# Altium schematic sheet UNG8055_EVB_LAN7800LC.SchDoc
size 416 x 264 mm; DocumentNumber: 2; SheetNumber: 2; SheetTotal: 2; PageTitle: LAN7800, RJ45 MagJack, USB Type-C Plug; PageSetup: Record=PageOptions¦CenterHorizontal=True¦CenterVertical=True¦PrintScale=1.02¦XCorrection=1.00¦YCorrection=1.00¦PrintKind=0¦BorderSize=5000000¦LeftOffset=0¦BottomOffset=0¦Orientation=2¦PaperLength=1000¦PaperWidth=1000¦Scale=100¦PaperSource=7¦PrintQuality=-3¦MediaType=1¦DitherType=10¦PrintScaleMode=1¦PaperKind=11 x 17¦PaperIndex=119
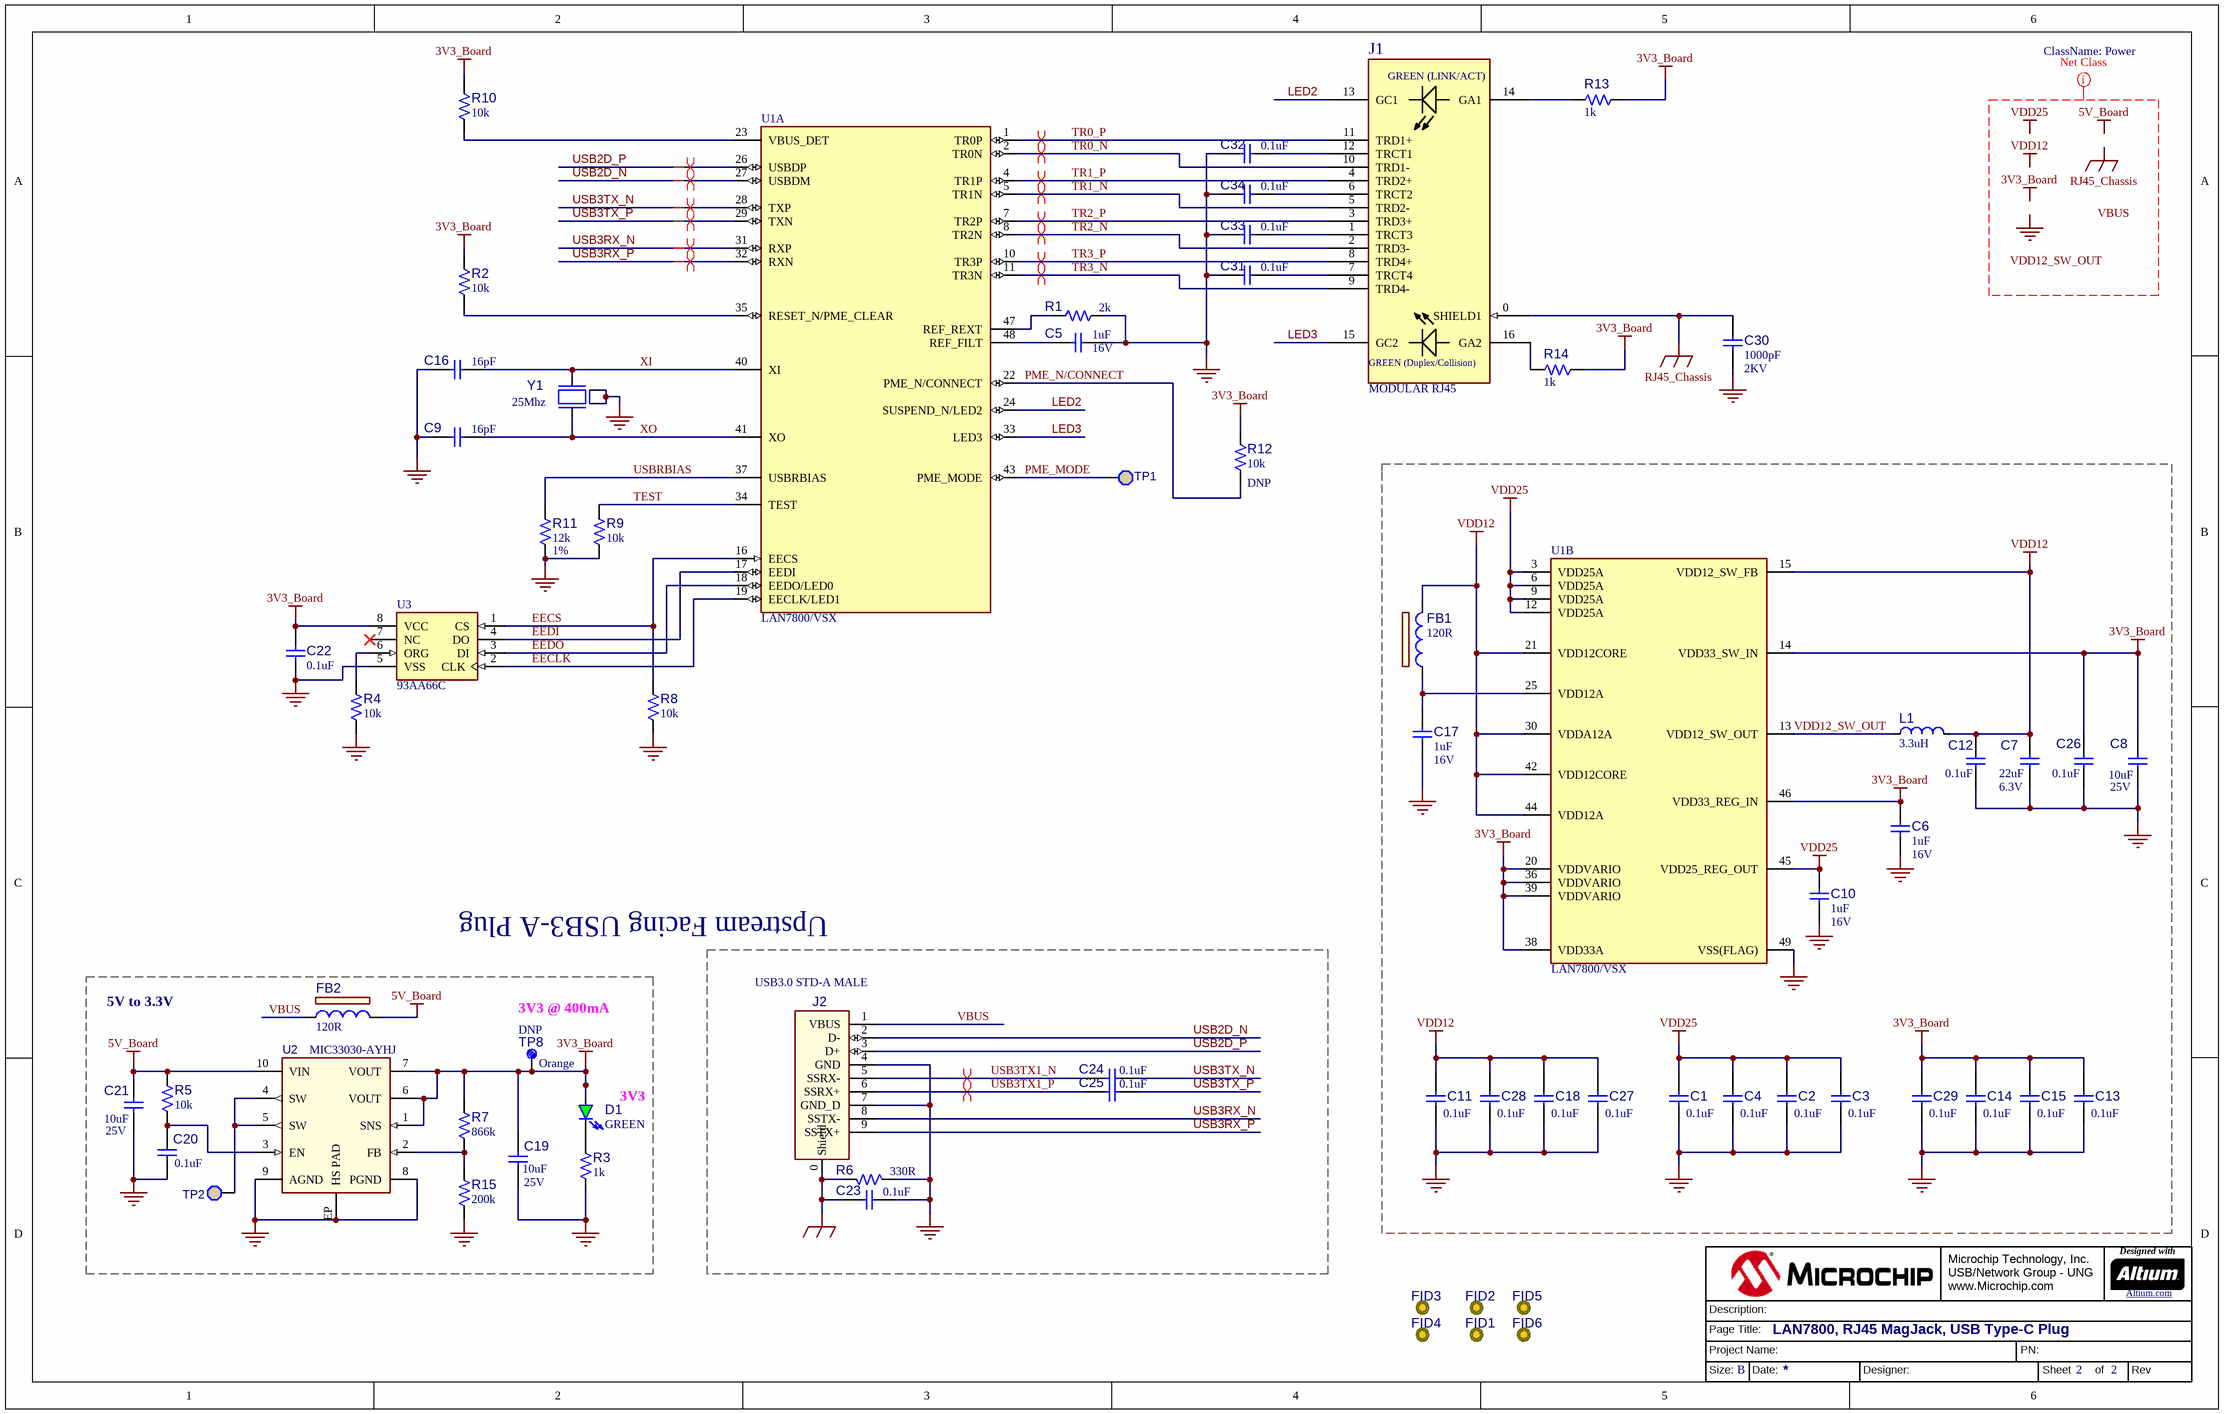
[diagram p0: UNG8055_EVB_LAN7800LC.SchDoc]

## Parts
?  (no value)  (graphical)
C1  value 0.1uF  [CAP_C_0402]  (hidden comment: Capacitor NP)
C2  value 0.1uF  [CAP_C_0402]  (hidden comment: Capacitor NP)
C3  value 0.1uF  [CAP_C_0402]  (hidden comment: Capacitor NP)
C4  value 0.1uF  [CAP_C_0402]  (hidden comment: Capacitor NP)
C5  value 1uF  Voltage: 16V  [CAP_C_0402]  (hidden comment: Capacitor NP)
C6  value 1uF  Voltage: 16V  [CAP_C_0402]  (hidden comment: Capacitor NP)
C7  value 22uF  Voltage: 6.3V  [CAP_C_0603]  (hidden comment: Capacitor NP)
C8  value 10uF  Voltage: 25V  [CAP_C_0603]  (hidden comment: Capacitor NP)
C9  value 16pF  [CAP_C_0402]  (hidden comment: Capacitor NP)
C10  value 1uF  Voltage: 16V  [CAP_C_0402]  (hidden comment: Capacitor NP)
C11  value 0.1uF  [CAP_C_0402]  (hidden comment: Capacitor NP)
C12  value 0.1uF  [CAP_C_0402]  (hidden comment: Capacitor NP)
C13  value 0.1uF  [CAP_C_0402]  (hidden comment: Capacitor NP)
C14  value 0.1uF  [CAP_C_0402]  (hidden comment: Capacitor NP)
C15  value 0.1uF  [CAP_C_0402]  (hidden comment: Capacitor NP)
C16  value 16pF  [CAP_C_0402]  (hidden comment: Capacitor NP)
C17  value 1uF  Voltage: 16V  [CAP_C_0402]  (hidden comment: Capacitor NP)
C18  value 0.1uF  [CAP_C_0402]  (hidden comment: Capacitor NP)
C19  value 10uF  Voltage: 25V  [CAP_C_0603]  (hidden comment: Capacitor NP)
C20  value 0.1uF  [CAP_C_0402]  (hidden comment: Capacitor NP)
C21  value 10uF  Voltage: 25V  [CAP_C_0603]  (hidden comment: Capacitor NP)
C22  value 0.1uF  [CAP_C_0402]  (hidden comment: Capacitor NP)
C23  value 0.1uF  [CAP_C_0402]  (hidden comment: Capacitor NP)
C24  value 0.1uF  [CAP_C_0402]  (hidden comment: Capacitor NP)
C25  value 0.1uF  [CAP_C_0402]  (hidden comment: Capacitor NP)
C26  value 0.1uF  [CAP_C_0402]  (hidden comment: Capacitor NP)
C27  value 0.1uF  [CAP_C_0402]  (hidden comment: Capacitor NP)
C28  value 0.1uF  [CAP_C_0402]  (hidden comment: Capacitor NP)
C29  value 0.1uF  [CAP_C_0402]  (hidden comment: Capacitor NP)
C30  value 1000pF  Voltage: 2KV  [CAP_C_1808]  (hidden comment: Capacitor NP)
C31  value 0.1uF  [CAP_C_0402]  (hidden comment: Capacitor NP)
C32  value 0.1uF  [CAP_C_0402]  (hidden comment: Capacitor NP)
C33  value 0.1uF  [CAP_C_0402]  (hidden comment: Capacitor NP)
C34  value 0.1uF  [CAP_C_0402]  (hidden comment: Capacitor NP)
D1  value GREEN  [LED_0603_GREEN]  (hidden comment: LED_green)
FB1  value 120R  [IND_C_0603]  (hidden comment: Ferrite Bead)
FB2  value 120R  [Ind_C_0603]  (hidden comment: Ferrite Bead)
FID1  FIDUCIAL  [FIDUCIAL]  (value not drawn)
FID2  FIDUCIAL  [FIDUCIAL]  (value not drawn)
FID3  FIDUCIAL  [FIDUCIAL]  (value not drawn)
FID4  FIDUCIAL  [FIDUCIAL]  (value not drawn)
FID5  FIDUCIAL  [FIDUCIAL]  (value not drawn)
FID6  FIDUCIAL  [FIDUCIAL]  (value not drawn)
J1  value MODULAR RJ45  [CON_JACK_RJ45_1PORT_LED_RJMG2012211A0FR]  (hidden comment: CON RJ-45 RJMG2012211A0FR)
J2  value USB3.0 STD-A MALE  [CON_USB3.0-A_PLUG_SMD_RA_WE_692112030100]  (hidden comment: CON USB3.0 A-B)
L1  value 3.3uH  [IND_WE_74404032033_L3W3H1.5]  (hidden comment: Inductor)
R1  value 2k  [RES_C_0402]  (hidden comment: Resistor)
R2  value 10k  [RES_C_0402]  (hidden comment: Resistor)
R3  value 1k  [RES_C_0603]  (hidden comment: Resistor)
R4  value 10k  [RES_C_0402]  (hidden comment: Resistor)
R5  value 10k  [RES_C_0402]  (hidden comment: Resistor)
R6  value 330R  [RES_C_0603]  (hidden comment: Resistor)
R7  value 866k  [RES_C_0603]  (hidden comment: Resistor)
R8  value 10k  [RES_C_0402]  (hidden comment: Resistor)
R9  value 10k  [RES_C_0402]  (hidden comment: Resistor)
R10  value 10k  [RES_C_0402]  (hidden comment: Resistor)
R11  value 12k  Tolerance: 1%  [RES_C_0402]  (hidden comment: Resistor)
R12  value 10k  Populated: DNP  [RES_C_0402]  (hidden comment: Resistor)
R13  value 1k  [RES_C_0603]  (hidden comment: Resistor)
R14  value 1k  [RES_C_0603]  (hidden comment: Resistor)
R15  value 200k  [RES_C_0603]  (hidden comment: Resistor)
TP1  Jumper  [TP_PAD_SMT_20OCTAGONAL]  (value not drawn)
TP2  Jumper  [TP_PAD_SMT_20OCTAGONAL]  (value not drawn)
TP8  value Orange  Populated: DNP  [CON_TP_TH_V_ORN_KEC_5003]  (hidden comment: Test Point)
U1  value LAN7800/VSX  [QFN-48_6X6]  (hidden comment: LAN7800 QFN-48 TEST)  (parts A,B of 2)
U2  value MIC33030-AYHJ  [MLF-10_2.5x2.0mm]  (hidden comment: MIC33030-AYHJ MLF-10)
U3  value 93AA66C  [SOIC-8_150MIL]  (hidden comment: 93XX66A_B_C PDIP-8_SOIC-8_TSSOP-8_MSOP-8)
Y1  value 25Mhz  [CRYSTAL_ABM8G]  (hidden comment: Crystal 4 Pins)

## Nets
3V3_Board: C6.2 C8.2 C13.2 C14.2 C15.2 C19.2 C22.2 C26.2 C29.2 D1.1(A) R2.2 R7.2 R10.2 R12.2 R13.2 R14.2 TP8.1 U1.14(VDD33_SW_IN) U1.20(VDDVARIO) U1.36(VDDVARIO) U1.38(VDD33A) U1.39(VDDVARIO) U1.46(VDD33_REG_IN) U2.1(SNS) U2.6(VOUT) U2.7(VOUT) U3.8(VCC)
5V_Board: C21.2 FB2.2 R5.2 U2.10(VIN)
Earth_gnd: C23.2 J2.0(Shield) R6.1
GND: C1.1 C2.1 C3.1 C4.1 C5.1 C6.1 C7.1 C8.1 C9.1 C10.1 C11.1 C12.1 C13.1 C14.1 C15.1 C16.1 C17.1 C18.1 C19.1 C20.1 C21.1 C22.1 C23.1 C26.1 C27.1 C28.1 C29.1 C30.1 C31.1 C32.1 C33.1 C34.1 J2.4(GND) J2.7(GND_D) R1.2 R3.1 R4.1 R6.2 R8.1 R9.1 R11.1 R15.1 U1.49(VSS(FLAG)) U2.8(PGND) U2.9(AGND) U2.EP(HS_PAD) U3.5(VSS) Y1.2(GND) Y1.4(GND)
RJ45_Chassis: C30.2 J1.0(SHIELD1)
VDD12: C7.2 C11.2 C12.2 C18.2 C27.2 C28.2 FB1.2 L1.2(F) U1.15(VDD12_SW_FB) U1.21(VDD12CORE) U1.30(VDDA12A) U1.42(VDD12CORE) U1.44(VDD12A)
VDD25: C1.2 C2.2 C3.2 C4.2 C10.2 U1.3(VDD25A) U1.6(VDD25A) U1.9(VDD25A) U1.12(VDD25A) U1.45(VDD25_REG_OUT)
EECLK: U1.19(EECLK/LED1) U3.2(CLK)
EECS: R8.2 U1.16(EECS) U3.1(CS)
EEDI: U1.17(EEDI) U3.4(DO)
EEDO: U1.18(EEDO/LED0) U3.3(DI)
LED2: J1.13(GC1) U1.24(SUSPEND_N/LED2)
LED3: J1.15(GC2) U1.33(LED3)
PME_MODE: TP1.1(P1) U1.43(PME_MODE)
PME_N/CONNECT: R12.1 U1.22(PME_N/CONNECT)
TEST: R9.2 U1.34(TEST)
TR0_N: J1.10(TRD1-) U1.2(TR0N)
TR0_P: J1.11(TRD1+) U1.1(TR0P)
TR1_N: J1.5(TRD2-) U1.5(TR1N)
TR1_P: J1.4(TRD2+) U1.4(TR1P)
TR2_N: J1.2(TRD3-) U1.8(TR2N)
TR2_P: J1.3(TRD3+) U1.7(TR2P)
TR3_N: J1.9(TRD4-) U1.11(TR3N)
TR3_P: J1.8(TRD4+) U1.10(TR3P)
USB2D_N: J2.2(D-) U1.27(USBDM)
USB2D_P: J2.3(D+) U1.26(USBDP)
USB3RX_N: J2.8(SSTX-) U1.31(RXP)
USB3RX_P: J2.9(SSTX+) U1.32(RXN)
USB3TX1_N: C24.1 J2.5(SSRX-)
USB3TX1_P: C25.1 J2.6(SSRX+)
USB3TX_N: C24.2 U1.28(TXP)
USB3TX_P: C25.2 U1.29(TXN)
USBRBIAS: R11.2 U1.37(USBRBIAS)
VBUS: FB2.1 J2.1(VBUS)
VDD12_SW_OUT: L1.1(S) U1.13(VDD12_SW_OUT)
XI: C16.2 U1.40(XI) Y1.3(Osc2)
XO: C9.2 U1.41(XO) Y1.1(Osc1)
NetC5_2: C5.2 U1.48(REF_FILT)
NetC17_2: C17.2 FB1.1 U1.25(VDD12A)
NetC20_2: C20.2 R5.1 U2.3(EN)
NetC31_2: C31.2 J1.7(TRCT4)
NetC32_2: C32.2 J1.12(TRCT1)
NetC33_2: C33.2 J1.1(TRCT3)
NetC34_2: C34.2 J1.6(TRCT2)
NetD1_2: D1.2(K) R3.2
NetJ1_14: J1.14(GA1) R13.1
NetJ1_16: J1.16(GA2) R14.1
NetR1_1: R1.1 U1.47(REF_REXT)
NetR2_1: R2.1 U1.35(RESET_N/PME_CLEAR)
NetR4_2: R4.2 U3.6(ORG)
NetR7_1: R7.1 R15.2 U2.2(FB)
NetR10_1: R10.1 U1.23(VBUS_DET)
NetTP2_1: TP2.1(P1) U2.4(SW) U2.5(SW)

Not connected (* = marked no-connect by the designer): U3 7(NC)*

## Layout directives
net class Power: 3V3_Board, 5V_Board, GND, RJ45_Chassis, VBUS, VDD12, VDD12_SW_OUT, VDD25
differential pair; net class GBE: TR0_N, TR0_P, TR1_N, TR1_P, TR2_N, TR2_P, TR3_N, TR3_P
differential pair; NetClass: USB3.: USB3RX_N, USB3RX_P, USB3TX1_N, USB3TX1_P, USB3TX_N, USB3TX_P
differential pair; NetClass: USB2.: USB2D_N, USB2D_P

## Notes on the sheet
- Upstream Facing USB3-A Plug
- 5V to 3.3V
- (near TP8) 3V3 @ 400mA
- (near D1) 3V3
- Labels drawn without touching a wire or pin: 3V3_Board, 5V_Board, GND, RJ45_Chassis, VBUS, VDD12, VDD12_SW_OUT, VDD25

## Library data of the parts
? = Title Block B_UNG1_Altium
C1-C4 C11-C15 C18 C22-C29 C31-C34 = CAP1337: Capacitor; Manufacturer 1: TDK Corporation; Manufacturer Part Number 1: CGA2B3X7R1V104K050BB; Voltage: 35V; Description_: CAP CER 0.1uF 35V 10% X7R SMD 0402; Dev Tools Status: Design; Tolerance: 10%; Temperature Coeffcient: X7R; Type: Ceramic; Owner: Sam Charles; Populated: YES
C5 C6 C10 C17 = CAP1065: Capacitor; Manufacturer 1: TDK Corporation; Manufacturer Part Number 1: C1005X5R1C105K; Description_: CAP CER 1uF 16V 10% X5R SMD 0402; Dev Tools Status: Production; Tolerance: 10%; Temperature Coeffcient: X5R; Type: Ceramic; Owner: Tad Ahlvers; Populated: YES
C7 = CAP1366: Capacitor; Manufacturer 1: Samsung Electro-Mechanics America, Inc; Manufacturer Part Number 1: CL10A226MQ8NRNC; Description_: CAP CER 22uF 6.3V 20% X5R SMD 0603; Dev Tools Status: Design; Temperature Coeffcient: X5R; Type: Ceramic; Populated: YES
C8 C19 C21 = CAP1461: Capacitor; Manufacturer 1: Murata Electronics North America; Manufacturer Part Number 1: GRM188R61E106MA73D; Description_: CAP CER 10UF 25V 20% X5R SMD 0603; Dev Tools Status: Production; Tolerance: ±20%; Temperature Coeffcient: X5R; Type: Ceramic; Owner: Tim Moffat; Populated: YES
C9 C16 = CAP1767: Capacitor; Manufacturer 1: Murata Electronics North America; Manufacturer Part Number 1: GRM1555C1H160JA01D; Voltage: 50V; Description_: CAP CER 16pF 50V 5% NP0 0402; Dev Tools Status: Design; Tolerance: 5%; Temperature Coeffcient: NPO; Type: Ceramic; Owner: Sam Charles; Populated: YES
C20 = CAP1337: Capacitor; Manufacturer 1: TDK Corporation; Manufacturer Part Number 1: CGA2B3X7R1V104K050BB; Voltage: 35V; Description_: CAP CER 0.1uF 35V 10% X7R SMD 0402; Dev Tools Status: Design; Tolerance: 10%; Temperature Coeffcient: X7R; Type: Ceramic; Owner: Sam Charles; Populated: Yes
C30 = CAP1775: Capacitor; Manufacturer 1: Murata Electronics North America; Manufacturer Part Number 1: GR442QR73D102KW01L; Description_: CAP CER 1000pF 2KV 10% X7R SMD 1808; Dev Tools Status: Design; Tolerance: 10%; Temperature Coeffcient: X7R; Type: Ceramic; Owner: Sam Charles; Populated: Yes
D1 = DIODE1155: LED; Manufacturer 1: Lite-On Inc; Manufacturer Part Number 1: LTST-C191KGKT; Description_: DIO LED GREEN 2V 30mA 35mcd Clear SMD 0603; Dev Tools Status: Production; Type: LED Single; Forward Current: 30mA; Power: 75mW; Reverse Voltage: 5V; Owner: Tad Ahlvers; Populated: YES
FB1 FB2 = FB1003: Manufacturer 1: TDK Corporation; Manufacturer Part Number 1: MMZ1608B121CTAH0; MCHP-ID: FB1003; Description_: FERRITE 600mA 120R SMD 0603; Dev Tools Status: Design; Owner: Jamus Griego; Populated: YES
FID1-FID6 = FIDUCIAL: Populated: DNP
J1 = CON1827: Manufacturer 1: Amphenol Commercial Products; Description_: CON MODULAR JACK RJ45 10/100/1000 MAGNETICS 2xLEDs SHIELD TH R/A; Dev Tools Status: Design; Owner: Jennifer Hancock; Populated: YES
J2 = CON1255: Connector USB; Manufacturer 1: Wurth Electronics Inc; Manufacturer Part Number 1: 692112030100; Description_: CON USB3.0 STD-A MALE SMD R/A; Dev Tools Status: Production; Owner: Bogdan Popescu; Voltage: 30V; Current: 1.8A; Populated: YES
L1 = IND1557: Manufacturer 1: Wurth Electronics Inc.; Manufacturer Part Number 1: 74404032033; Description_: INDUCTOR 3.3uH 1.5A 20% SMD L3W3H1.5; Dev Tools Status: Design; Owner: Sam Charles; DCR: 0.070R; Saturation Current: 1.5A; Test Frequency: 100kHz; Populated: YES
R1 = RES1437: Manufacturer 1: Panasonic Electronic Components; Manufacturer Part Number 1: ERJ-2RKF2001X; Tolerance: 1%; Description_: RES TKF 2k 1% 1/10W SMD 0402; Dev Tools Status: Design; Temperature Coeffcient: ±100ppm/°C; Power: 1/10W; Populated: YES
R2 R4 R5 R8-R10 = RSMT1019: Manufacturer 1: Panasonic; Manufacturer Part Number 1: ERJ-2RKF1002X; Tolerance: 1%; Description_: RES TKF 10k 1% 1/10W SMD 0402; Dev Tools Status: Production; Voltage: 50V; Temperature Coeffcient: 100ppm/C; Power: 1/10W; Owner: Brent Lanphear; Populated: Yes
R3 R13 R14 = RSMT0047: Manufacturer 1: Panasonic; Manufacturer Part Number 1: ERJ-3GEYJ102V; Tolerance: 5%; Description_: RES TKF 1k 5% 1/10W SMD 0603; Voltage: 75V; Temperature Coeffcient: 200ppm/C; Power: 1/10W; Populated: Yes
R6 = RES1346: Manufacturer 1: Panasonic Electronic Components; Manufacturer Part Number 1: ERA-V33J331V; Tolerance: 5%; Description_: RES MF 330R 5% 1/16W SMD 0603; Temperature Coeffcient: 3300ppm/C; Circuit Type: Isolated; Power: 1/16W; Owner: Jairuz Agang-ang; Populated: YES
R7 = RSMT1204: Manufacturer 1: Yageo; Manufacturer Part Number 1: RC0603FR-07866KL; Tolerance: 1%; Description_: RES TKF 866k 1% 1/10W SMD 0603; Dev Tools Status: Design; Voltage: 75V; Temperature Coeffcient: 100ppm/C; Power: 1/10W; Owner: Alexandru Chiser - M19201; Populated: YES
R11 = RES1021: Manufacturer 1: Rohm Semiconductor; Manufacturer Part Number 1: MCR01MZPF1202; Description_: RES TKF 12k 1% 1/16W SMD 0402; Dev Tools Status: Production; Voltage: 50V; Temperature Coeffcient: 400ppm/C; Power: 1/16W; Owner: Tad Ahlvers; Populated: YES
R12 = RSMT1019: Manufacturer 1: Panasonic; Manufacturer Part Number 1: ERJ-2RKF1002X; Tolerance: 1%; Description_: RES TKF 10k 1% 1/10W SMD 0402; Dev Tools Status: Production; Voltage: 50V; Temperature Coeffcient: 100ppm/C; Power: 1/10W; Owner: Brent Lanphear
R15 = RES1140: Manufacturer 1: Vishay; Manufacturer Part Number 1: CRCW0603200KFKEA; Tolerance: 1%; Description_: RES TKF 200k 1% 1/10W SMD 0603; Dev Tools Status: Production; Voltage: 75V; Temperature Coeffcient: 100ppm/C; Power: 1/10W; Owner: Mihai T(M91442); Populated: Yes
TP1 TP2 = TEST PAD SMT 20 OCTAGON: Manufacturer Part Number: none; Description_: TEST Pad,SMT, 20MIL OCTAGON pad; Populated: Yes
TP8 = CON1282: Manufacturer 1: Keystone Electronics; Manufacturer Part Number 1: 5003; Description_: CON TP LOOP Orange TH; Dev Tools Status: Design; Owner: Stephen Humberd
U1 = MIC7903: Manufacturer 1: Microchip Technology Inc; Description_: MCHP INTERFACE ETHERNET LAN7800/VSX QFN-48; Dev Tools Status: Design; Owner: Jennifer Hancock; Populated: YES
U2 = MIC7400: Manufacturer 1: Microchip; Manufacturer Part Number 1: MIC33030-AYHJ-TR; Description_: MCHP ANALOG 8MHz PWM 0.4A INTERNAL INDUCTOR BUCK REGULATOR MIC33030 MLF-10; Dev Tools Status: Design; Owner: Severino Balong Jr.; Populated: YES
U3 = MIC7670: Manufacturer 1: Microchip Technology; Manufacturer Part Number 1: 93AA66C-I/SN; Description_: MCHP MEMORY SERIAL EEPROM 4k Microwire 93AA66C-I/SN SOIC-8; MAPS Description: 4K, 512 X 8 or 256 X 16 SERIAL EE, 1.8V; Dev Tools Status: Design; Owner: Sam Charles; MPC: C5BJ37C2XC00; PackingMedia: TUBE; TempRange: -40C to +85C; Stage: REL; LeadCount: 8; PackageWidth: 3.90mm(.150in); ForceMinOrderQtyMult: False; MinOrderQty: 0; LeadContent: Pb-FREE; MemorySize: 4K; OpVoltMin: 1.8; OpVoltMax: 5.5; MaxClockFreq: 3 MHz; WPScheme: None; MemoryOrg: x8, x16; Endurance: 1,000,000; Populated: YES
Y1 = OSC1196: Manufacturer 1: Abracon LLC; Manufacturer Part Number 1: ABM8G-25.000MHZ-B4Y-T; Description_: CRYSTAL 25MHz 10pF SMD ABM8G; Dev Tools Status: Design; Owner: Sam Charles; Tolerance: ±30ppm; Load Capacitance: 10pF; Populated: YES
